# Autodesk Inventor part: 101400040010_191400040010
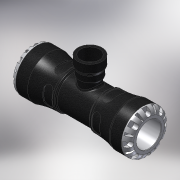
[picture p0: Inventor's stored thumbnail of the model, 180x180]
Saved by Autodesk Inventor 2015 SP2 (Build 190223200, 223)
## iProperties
Created: 2016-12
Part Number: 101400040010_191400040010
Material: PVC-Piping
Description: PLASSON TEE WITH THREADED FEMALE OFFTAKE 40X1" SERIES 1
Document SubType Name: Modeling
Designer: KIM
Mass: 507.831 g
Surface Area: 782.915 cm^2
Volume: 362.737 cm^3
Density: 1.4 g/cm^3
Appearance: Black Cast
Author: KIM
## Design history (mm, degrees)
derived "1014.ipt"
feature "Solid1::1014.ipt"
tag "TaggingFeature1"
body "Solid1"
other parameters: "d1" = 29.4, "d8" = 59.5, "d13" = 8, "d14" = 8, "d15" = 0, "d17" = 360 deg, "d19" = 8 deg, "d20" = 0.8, "d21" = 0.8, "d22" = 8 deg, "d24" = 0, "d26" = 360 deg, "d33" = 7, "d43" = 54.6, "d51" = 0.7, "d54" = 14, "d55" = 8.8, "d57" = 15.68, "d58" = 0, "d74" = 0, "d77" = 3.33333, "d79" = 54.6, "d80" = 192, "d82" = 0.8, "d115" = 360 deg, "d139" = 8, "d140" = 0, "d142" = 360 deg, "d207" = 90 deg, "d228" = 11.9, "d247" = 1.4, "d248" = 4.2, "d266" = 0, "d268" = 30.291, "d270" = 4.54365, "d271" = 7, "d274" = 2.27183, "d275" = 65, "d276" = 3.0291, "d277" = 3.0291, "d278" = 3.0291, "d279" = 3.0291, "d281" = 0, "d282" = 21, "A_" = 65, "H_" = 192, "Rp_" = 30.291, "l_2" = 21, "d9" = 10
